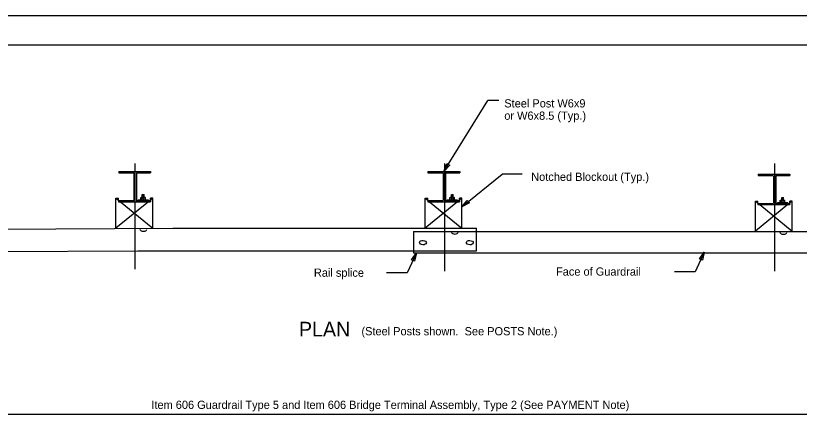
# Model space of a CAD drawing. Extents: x 0 to 34, y 0 to 22.
# Drawn here: x 8.33 to 21.69, y 15.07 to 22 of the extents above; entities that cross this region are included whole.
import ezdxf

# ---------------------------------------------------------------- set-up
doc = ezdxf.new("R2010")
doc.units = 0
for name, color, linetype in [('SH_Border', 7, 'Continuous'), ('SH_Cut_Line', 7, 'Continuous'), ('ST_Details', 7, 'Continuous'), ('ST_Text', 7, 'Continuous')]:
    doc.layers.add(name, color=color, linetype=linetype)

msp = doc.modelspace()

# ---------------------------------------------------------------- linework, layer by layer
at = {"layer": 'SH_Border'}
msp.add_lwpolyline([(2, 21.5), (33.5, 21.5), (33.5, 0.5), (2, 0.5)], close=True, dxfattribs=at)
at = {"layer": 'SH_Cut_Line'}
msp.add_lwpolyline([(0, 0), (34, 0), (34, 22), (0, 22)], close=True, dxfattribs=at)
at = {"layer": 'ST_Details'}
for p, q in [((10.372, 17.68), (10.372, 19.48)), ((15.642, 19.48), (15.642, 17.646)), ((21.271, 19.48), (21.271, 17.646)), ((10.09, 19.345), (10.631, 19.345)), ((10.092, 19.344), (10.092, 19.322)), ((10.092, 19.322), (10.35, 19.322)), ((10.351, 19.319), (10.351, 18.847)), ((10.392, 19.322), (10.634, 19.322)), ((10.392, 19.321), (10.392, 18.845)), ((10.634, 19.344), (10.634, 19.322)), ((15.36, 19.345), (15.9, 19.345)), ((15.362, 19.344), (15.362, 19.322)), ((15.362, 19.322), (15.619, 19.322)), ((15.621, 19.319), (15.621, 18.847)), ((15.661, 19.322), (15.904, 19.322)), ((15.661, 19.321), (15.661, 18.845)), ((15.904, 19.344), (15.904, 19.322)), ((20.989, 19.296), (21.529, 19.296)), ((20.991, 19.295), (20.991, 19.273)), ((20.991, 19.273), (21.248, 19.273)), ((21.25, 19.27), (21.25, 18.798)), ((21.29, 19.273), (21.533, 19.273)), ((21.29, 19.272), (21.29, 18.796)), ((21.533, 19.295), (21.533, 19.273)), ((10.044, 18.374), (10.044, 18.889)), ((10.044, 18.889), (10.089, 18.889)), ((10.044, 18.889), (10.089, 18.853)), ((10.089, 18.846), (10.089, 18.889)), ((10.089, 18.846), (10.089, 18.827)), ((10.089, 18.846), (10.35, 18.846)), ((10.39, 18.846), (10.631, 18.846)), ((10.421, 18.861), (10.592, 18.861)), ((10.421, 18.861), (10.421, 18.846)), ((10.466, 18.902), (10.546, 18.902)), ((10.466, 18.862), (10.466, 18.902)), ((10.491, 18.862), (10.491, 18.902)), ((10.493, 18.903), (10.493, 18.949)), ((10.493, 18.949), (10.522, 18.949)), ((10.493, 18.941), (10.522, 18.941)), ((10.493, 18.934), (10.522, 18.934)), ((10.493, 18.927), (10.522, 18.927)), ((10.493, 18.92), (10.522, 18.92)), ((10.493, 18.914), (10.522, 18.914)), ((10.493, 18.907), (10.522, 18.907)), ((10.521, 18.862), (10.521, 18.902)), ((10.522, 18.903), (10.522, 18.949)), ((10.546, 18.862), (10.546, 18.902)), ((10.592, 18.861), (10.592, 18.846)), ((10.631, 18.846), (10.631, 18.889)), ((10.672, 18.889), (10.631, 18.889)), ((10.672, 18.889), (10.631, 18.855)), ((10.631, 18.846), (10.631, 18.827)), ((10.672, 18.374), (10.672, 18.889)), ((15.314, 18.374), (15.314, 18.889)), ((15.314, 18.889), (15.359, 18.889)), ((15.314, 18.889), (15.359, 18.853)), ((15.359, 18.846), (15.359, 18.889)), ((15.359, 18.846), (15.359, 18.827)), ((15.359, 18.846), (15.619, 18.846)), ((15.66, 18.846), (15.9, 18.846)), ((15.691, 18.861), (15.862, 18.861)), ((15.691, 18.861), (15.691, 18.846)), ((15.736, 18.902), (15.815, 18.902)), ((15.736, 18.862), (15.736, 18.902)), ((15.761, 18.862), (15.761, 18.902)), ((15.763, 18.903), (15.763, 18.949)), ((15.763, 18.949), (15.792, 18.949)), ((15.763, 18.941), (15.792, 18.941)), ((15.763, 18.934), (15.792, 18.934)), ((15.763, 18.927), (15.792, 18.927)), ((15.763, 18.92), (15.792, 18.92)), ((15.763, 18.914), (15.792, 18.914)), ((15.763, 18.907), (15.792, 18.907)), ((15.79, 18.862), (15.79, 18.902)), ((15.792, 18.903), (15.792, 18.949)), ((15.815, 18.862), (15.815, 18.902)), ((15.862, 18.861), (15.862, 18.846)), ((15.9, 18.846), (15.9, 18.889)), ((15.942, 18.889), (15.9, 18.889)), ((15.942, 18.889), (15.9, 18.855)), ((15.9, 18.846), (15.9, 18.827)), ((15.942, 18.374), (15.942, 18.889)), ((20.943, 18.325), (20.943, 18.84)), ((20.943, 18.84), (20.987, 18.84)), ((20.943, 18.84), (20.987, 18.804)), ((20.987, 18.797), (20.987, 18.84)), ((21.364, 18.854), (21.444, 18.854)), ((21.364, 18.813), (21.364, 18.854)), ((21.389, 18.813), (21.389, 18.854)), ((21.392, 18.854), (21.392, 18.9)), ((21.392, 18.9), (21.421, 18.9)), ((21.392, 18.893), (21.421, 18.893)), ((21.392, 18.885), (21.421, 18.885)), ((21.392, 18.878), (21.421, 18.878)), ((21.392, 18.871), (21.421, 18.871)), ((21.392, 18.865), (21.421, 18.865)), ((21.392, 18.858), (21.421, 18.858)), ((21.419, 18.813), (21.419, 18.854)), ((21.421, 18.854), (21.421, 18.9)), ((21.444, 18.813), (21.444, 18.854)), ((21.529, 18.797), (21.529, 18.84)), ((21.571, 18.84), (21.529, 18.84)), ((21.571, 18.84), (21.529, 18.806)), ((21.571, 18.325), (21.571, 18.84)), ((10.597, 18.827), (10.044, 18.374)), ((10.089, 18.827), (10.631, 18.827)), ((10.12, 18.827), (10.672, 18.374)), ((15.867, 18.827), (15.314, 18.374)), ((15.359, 18.827), (15.9, 18.827)), ((15.39, 18.827), (15.942, 18.374)), ((21.496, 18.778), (20.943, 18.325)), ((20.987, 18.797), (20.987, 18.778)), ((20.987, 18.797), (21.248, 18.797)), ((20.987, 18.778), (21.529, 18.778)), ((21.018, 18.778), (21.571, 18.325)), ((21.289, 18.797), (21.529, 18.797)), ((21.319, 18.812), (21.491, 18.812)), ((21.319, 18.812), (21.319, 18.797)), ((21.491, 18.812), (21.491, 18.797)), ((21.529, 18.797), (21.529, 18.778)), ((4.527, 18.338), (11.012, 18.374)), ((11.012, 18.374), (16.192, 18.374)), ((15.115, 18.319), (19.584, 18.319)), ((15.115, 18.319), (15.115, 17.955)), ((15.642, 18.374), (15.642, 18.204)), ((16.192, 18.319), (16.192, 18.374)), ((16.192, 17.993), (16.192, 18.319)), ((19.584, 18.319), (28.9, 18.319)), ((4.527, 17.954), (10.414, 17.993)), ((10.414, 17.993), (15.115, 17.993)), ((15.115, 17.993), (16.192, 17.993)), ((15.115, 17.955), (19.584, 17.955)), ((19.584, 17.955), (28.08, 17.955))]:
    msp.add_line(p, q, dxfattribs=at)
for centre, major_axis, ratio, start_param, end_param in [((10.478, 18.888), (0, -0.0145), 0.944544, 1.407332, 4.875992), ((10.507, 18.888), (0, -0.0151), 0.944544, 1.46268, 4.897879), ((10.533, 18.888), (0, -0.0127), 0.944544, 1.349184, 4.841957), ((15.748, 18.888), (0, -0.0145), 0.944544, 1.407332, 4.875992), ((15.777, 18.888), (0, -0.0151), 0.944544, 1.46268, 4.897879), ((15.803, 18.888), (0, -0.0127), 0.944544, 1.349184, 4.841957), ((21.377, 18.839), (0, -0.0145), 0.944544, 1.407332, 4.875992), ((21.406, 18.839), (0, -0.0151), 0.944544, 1.46268, 4.897879), ((21.432, 18.839), (0, -0.0127), 0.944544, 1.349184, 4.841957), ((10.51, 18.362), (-0.059, 0.0039), 0.623742, 0.247265, 3.105972), ((15.819, 18.313), (-0.059, 0.0039), 0.623742, 0.247265, 3.105972), ((15.64, 18.981), (0, 0.849), 0.944544, 3.899262, 3.900648), ((21.419, 18.309), (-0.059, 0.0039), 0.623742, 0.247265, 3.105972)]:
    msp.add_ellipse(centre, major_axis=major_axis, ratio=ratio, start_param=start_param, end_param=end_param, dxfattribs=at)
for centre in [(15.277, 18.13), (16.076, 18.13)]:
    msp.add_ellipse(centre, major_axis=(-0.059, 0.0039), ratio=0.623742, dxfattribs=at)
at = {"layer": 'ST_Text'}
for p, q in [((15.635, 19.345), (16.383, 20.555)), ((16.572, 20.555), (16.383, 20.555)), ((15.942, 18.74), (16.624, 19.297)), ((16.97, 19.297), (16.624, 19.297)), ((15.164, 17.955), (15.01, 17.615)), ((20.072, 17.969), (19.919, 17.63)), ((15.01, 17.615), (14.654, 17.615)), ((19.919, 17.63), (19.563, 17.63)), ((5.07, 15.205), (25.314, 15.205))]:
    msp.add_line(p, q, dxfattribs=at)
for points in [[(15.685, 19.479), (15.733, 19.45), (15.635, 19.345)], [(16.033, 18.851), (16.068, 18.807), (15.942, 18.74)], [(15.132, 17.816), (15.081, 17.839), (15.164, 17.955)], [(20.04, 17.83), (19.989, 17.853), (20.072, 17.969)]]:
    msp.add_lwpolyline(points, close=True, dxfattribs=at)

# ---------------------------------------------------------------- texts
for s, height, p in [('Steel Post W6x9', 0.14, (16.663, 20.435)), ('or W6x8.5 (Typ.)', 0.14, (16.663, 20.225)), ('Notched Blockout (Typ.)', 0.14, (17.122, 19.183)), ('Rail splice', 0.14, (13.418, 17.548)), ('Face of Guardrail', 0.14, (17.545, 17.567)), ('PLAN ', 0.25, (13.163, 16.53)), (' (Steel Posts shown.  See POSTS Note.)', 0.14, (14.176, 16.55)), ('Item 606 Guardrail Type 5 and Item 606 Bridge Terminal Assembly, Type 2 (See PAYMENT Note)', 0.14, (10.647, 15.295))]:
    msp.add_text(s, height=height, dxfattribs=at).set_placement(p)

doc.saveas('drawing.dxf')
